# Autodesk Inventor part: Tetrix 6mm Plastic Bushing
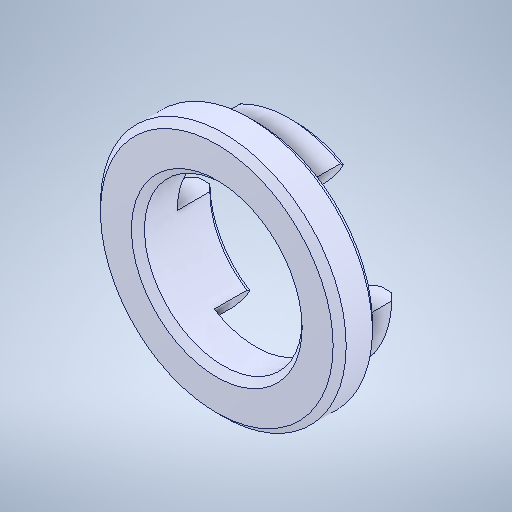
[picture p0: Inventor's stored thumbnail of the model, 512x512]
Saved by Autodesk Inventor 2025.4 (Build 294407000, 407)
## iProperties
Created: 2021-10
Part Number: Tetrix 6mm Plastic Bushing
Material: Genérico
Document SubType Name: Modeling
Designer: usuario
Density: 1 g/cm^3
Appearance: Valor por defecto
Author: usuario
Sending System: SolidWorks 2016
Last Author: LENOVO
Last Saved: 2021-10-26
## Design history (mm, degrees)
chamfer "Chamfer1"
node "Plane1"
node "Sólido1"
